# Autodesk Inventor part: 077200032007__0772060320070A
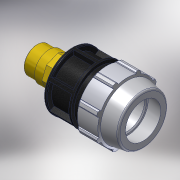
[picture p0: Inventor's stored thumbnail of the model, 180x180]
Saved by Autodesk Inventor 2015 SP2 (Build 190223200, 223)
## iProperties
Created: 2017-02
Part Number: 077200032007__0772060320070A
Material: PVC-Piping
Description: PLASSON MALE ADAPTOR INTEGRAL BRASS THREAD 32-3/4"
Document SubType Name: Modeling
Designer: KIM
Mass: 92.6774 g
Surface Area: 199.44 cm^2
Volume: 66.1981 cm^3
Density: 1.4 g/cm^3
Appearance: PTFE
Author: KIM
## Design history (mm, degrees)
derived "07720.ipt"
feature "Solid1::07720.ipt"
tag "TaggingFeature1"
body "Solid1"
other parameters: "d2" = 32, "d4" = 19.85714, "d5" = 19.85714, "d7" = 64, "d8" = 48, "d9" = 19.85714, "d11" = 3.97143, "d12" = 51.2, "d13" = 120 deg, "d14" = 48, "d15" = 10 deg, "d16" = 57.6, "d18" = 1.6, "d19" = 35 deg, "d20" = 17.5 deg, "d21" = 59.52, "d23" = 0, "d25" = 360 deg, "d27" = 1.28, "d34" = 3.2, "d36" = 0, "d42" = 27.8, "d43" = 1.92, "d46" = 0.96, "d49" = 83, "d51" = 139, "d53" = 0.64, "d55" = 360 deg, "d59" = 27.8, "d60" = 26.441, "d61" = 27.76305, "d62" = 18, "d63" = 46.33333, "d64" = 18.5087, "d65" = 139, "d66" = 16.31304, "d67" = 0, "d68" = 0.64, "d71" = 30 deg, "d72" = 23.7969, "d_" = 32, "E_" = 64, "H_" = 139, "l_" = 83, "l_2" = 18, "R_" = 26.441, "d73" = 27.1884
